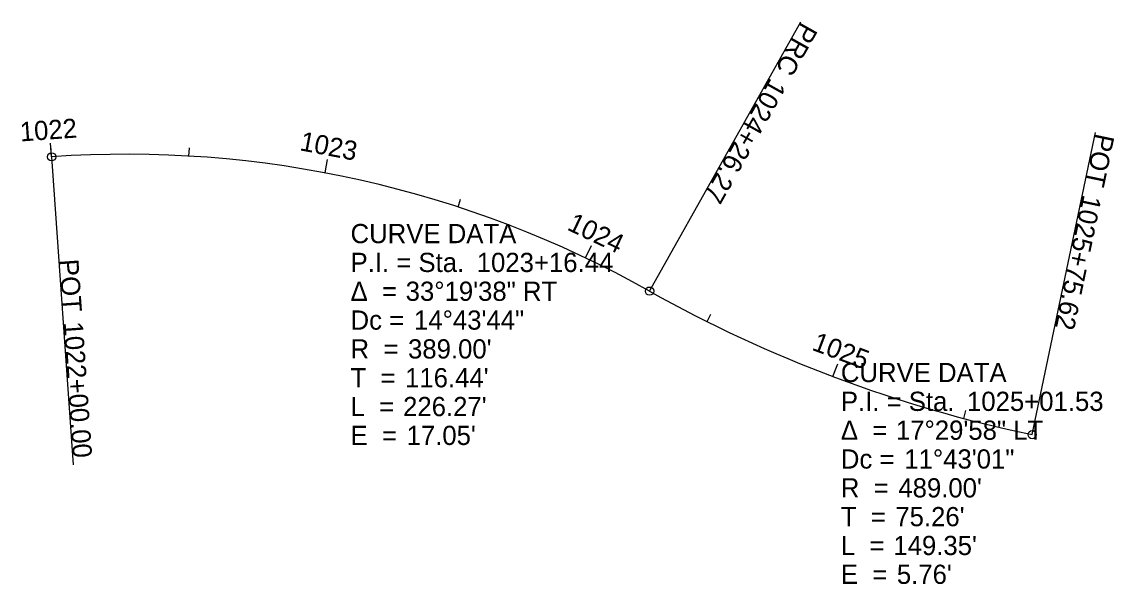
# Model space of a CAD drawing. Extents: x 2197198 to 2197596, y 661573 to 661777.
import ezdxf

# ---------------------------------------------------------------- set-up
doc = ezdxf.new("R2010")
doc.units = 0
for name, color, linetype in [('_CIVIL_CONSTRUCTION', 7, 'Continuous'), ('GE_X_Alignment', 7, 'Continuous'), ('GE_X_Alignment_1000_Curve_Data', 7, 'Continuous'), ('GE_X_Alignment_1000_Stations', 7, 'Continuous'), ('GE_X_Alignment_100_Curve_Data', 7, 'Continuous'), ('GE_X_Alignment_100_Stations', 7, 'Continuous'), ('GE_X_Alignment_500_Curve_Data', 7, 'Continuous'), ('GE_X_Alignment_500_Stations', 7, 'Continuous'), ('SC_Scratch2', 7, 'Continuous'), ('SC_Scratch5', 7, 'Continuous')]:
    doc.layers.add(name, color=color, linetype=linetype)

msp = doc.modelspace()

# ---------------------------------------------------------------- linework, layer by layer
at = {"layer": 'GE_X_Alignment'}
for p, q in [((2197426.98, 661679.27), (2197482.08, 661777.36)), ((2197566.26, 661626.99), (2197589.31, 661737.1)), ((2197209.31, 661728.18), (2197217.16, 661615.95))]:
    msp.add_line(p, q, dxfattribs=at)
for centre in [(2197209.31, 661728.18), (2197426.98, 661679.27), (2197566.26, 661626.99)]:
    msp.add_circle(centre, 1.5, dxfattribs=at)
at = {"layer": 'GE_X_Alignment_1000_Stations'}
for p, q in [((2197426.98, 661679.27), (2197482.08, 661777.36)), ((2197566.26, 661626.99), (2197589.31, 661737.1)), ((2197209.31, 661728.18), (2197217.16, 661615.95))]:
    msp.add_line(p, q, dxfattribs=at)
for centre in [(2197209.31, 661728.18), (2197426.98, 661679.27), (2197566.26, 661626.99)]:
    msp.add_circle(centre, 1.5, dxfattribs=at)
at = {"layer": 'GE_X_Alignment_100_Curve_Data'}
for p, q in [((2197426.98, 661679.27), (2197482.08, 661777.36)), ((2197566.26, 661626.99), (2197589.31, 661737.1)), ((2197209.31, 661728.18), (2197217.16, 661615.95))]:
    msp.add_line(p, q, dxfattribs=at)
for centre in [(2197209.31, 661728.18), (2197426.98, 661679.27), (2197566.26, 661626.99)]:
    msp.add_circle(centre, 1.5, dxfattribs=at)
at = {"layer": 'GE_X_Alignment_100_Stations'}
for p, q in [((2197209.31, 661728.18), (2197208.96, 661733.16)), ((2197259.28, 661728.46), (2197259.45, 661731.45)), ((2197308.86, 661722.33), (2197309.79, 661727.24)), ((2197357.26, 661709.89), (2197358.19, 661712.74)), ((2197403.66, 661691.36), (2197405.81, 661695.87)), ((2197447.94, 661668.16), (2197449.28, 661670.84)), ((2197493.73, 661648.14), (2197495.5, 661652.81)), ((2197541.33, 661632.89), (2197542.1, 661635.79))]:
    msp.add_line(p, q, dxfattribs=at)
at = {"layer": 'GE_X_Alignment_500_Curve_Data'}
for p, q in [((2197209.31, 661728.18), (2197209.1, 661731.17)), ((2197308.86, 661722.33), (2197309.42, 661725.27)), ((2197403.66, 661691.36), (2197404.95, 661694.07)), ((2197493.73, 661648.14), (2197495.5, 661652.81))]:
    msp.add_line(p, q, dxfattribs=at)
at = {"layer": 'SC_Scratch2'}
msp.add_line((2197493.73, 661648.14), (2197494.79, 661650.94), dxfattribs=at)
at = {"layer": 'SC_Scratch5'}
for centre, radius, start, end in [((2197236.45, 661340.13), 389, 60.6741, 94.0013), ((2197666.48, 662105.61), 489, 240.6741, 258.1734)]:
    msp.add_arc(centre, radius, start, end, dxfattribs=at)

# ---------------------------------------------------------------- texts
at = {"layer": '_CIVIL_CONSTRUCTION'}
for s, p in [('CURVE DATA', (2197318.14, 661696.73)), ('P.I. = Sta. ', (2197318.14, 661686.23)), ('1023+16.44', (2197364.07, 661686.23)), ('Δ  = ', (2197318.14, 661675.73)), ('33°19\'38" RT', (2197338.2, 661675.73)), ('Dc = ', (2197318.14, 661665.23)), ('14°43\'44"', (2197341.24, 661665.23)), ('R  = ', (2197318.14, 661654.73)), ("389.00'", (2197339.06, 661654.73)), ('T  = ', (2197318.14, 661644.23)), ("116.44'", (2197337.98, 661644.23)), ('CURVE DATA', (2197496.62, 661646.13)), ('L  = ', (2197318.14, 661633.73)), ("226.27'", (2197337.26, 661633.73)), ('P.I. = Sta. ', (2197496.62, 661635.63)), ('1025+01.53', (2197542.54, 661635.63)), ('Δ  = ', (2197496.62, 661625.13)), ('17°29\'58" LT', (2197516.67, 661625.13)), ('E  = ', (2197318.14, 661623.23)), ("17.05'", (2197338.53, 661623.23)), ('Dc = ', (2197496.62, 661614.63)), ('11°43\'01"', (2197519.71, 661614.63)), ('R  = ', (2197496.62, 661604.13)), ("489.00'", (2197517.54, 661604.13)), ('T  = ', (2197496.62, 661593.63)), ("75.26'", (2197516.45, 661593.63)), ('L  = ', (2197496.62, 661583.13)), ("149.35'", (2197515.73, 661583.13)), ('E  = ', (2197496.62, 661572.63)), ("5.76'", (2197517, 661572.63))]:
    msp.add_text(s, height=7, dxfattribs=at).set_placement(p)
at = {"layer": 'GE_X_Alignment'}
for s, rotation, p in [('PRC', 240.6741, (2197482.34, 661777.59)), ('1024+26.27', 240.6741, (2197470.9, 661757.22)), ('POT', 258.1734, (2197589.41, 661736.98)), ('1025+75.62', 258.1734, (2197584.73, 661714.64)), ('POT', 274.0013, (2197212.05, 661690.69)), ('1022+00.00', 274.0013, (2197213.64, 661667.92))]:
    msp.add_text(s, height=7, rotation=rotation, dxfattribs=at).set_placement(p)
at = {"layer": 'GE_X_Alignment_1000_Curve_Data'}
for s, p in [('CURVE DATA', (2197318.14, 661696.73)), ('P.I. = Sta. ', (2197318.14, 661686.23)), ('1023+16.44', (2197364.07, 661686.23)), ('Δ  = ', (2197318.14, 661675.73)), ('33°19\'38" RT', (2197338.2, 661675.73)), ('Dc = ', (2197318.14, 661665.23)), ('14°43\'44"', (2197341.24, 661665.23)), ('R  = ', (2197318.14, 661654.73)), ("389.00'", (2197339.06, 661654.73)), ('T  = ', (2197318.14, 661644.23)), ("116.44'", (2197337.98, 661644.23)), ('CURVE DATA', (2197496.62, 661646.13)), ('L  = ', (2197318.14, 661633.73)), ("226.27'", (2197337.26, 661633.73)), ('P.I. = Sta. ', (2197496.62, 661635.63)), ('1025+01.53', (2197542.54, 661635.63)), ('Δ  = ', (2197496.62, 661625.13)), ('17°29\'58" LT', (2197516.67, 661625.13)), ('E  = ', (2197318.14, 661623.23)), ("17.05'", (2197338.53, 661623.23)), ('Dc = ', (2197496.62, 661614.63)), ('11°43\'01"', (2197519.71, 661614.63)), ('R  = ', (2197496.62, 661604.13)), ("489.00'", (2197517.54, 661604.13)), ('T  = ', (2197496.62, 661593.63)), ("75.26'", (2197516.45, 661593.63)), ('L  = ', (2197496.62, 661583.13)), ("149.35'", (2197515.73, 661583.13)), ('E  = ', (2197496.62, 661572.63)), ("5.76'", (2197517, 661572.63))]:
    msp.add_text(s, height=7, dxfattribs=at).set_placement(p)
at = {"layer": 'GE_X_Alignment_1000_Stations'}
for s, rotation, p in [('PRC', 240.6741, (2197482.34, 661777.59)), ('1024+26.27', 240.6741, (2197470.9, 661757.22)), ('POT', 258.1734, (2197589.41, 661736.98)), ('1025+75.62', 258.1734, (2197584.73, 661714.64)), ('POT', 274.0013, (2197212.05, 661690.69)), ('1022+00.00', 274.0013, (2197213.64, 661667.92))]:
    msp.add_text(s, height=7, rotation=rotation, dxfattribs=at).set_placement(p)
at = {"layer": 'GE_X_Alignment_100_Curve_Data'}
for s, rotation, p in [('PRC', 240.6741, (2197482.34, 661777.59)), ('1024+26.27', 240.6741, (2197470.9, 661757.22)), ('POT', 258.1734, (2197589.41, 661736.98)), ('1025+75.62', 258.1734, (2197584.73, 661714.64)), ('POT', 274.0013, (2197212.05, 661690.69)), ('1022+00.00', 274.0013, (2197213.64, 661667.92))]:
    msp.add_text(s, height=7, rotation=rotation, dxfattribs=at).set_placement(p)
at = {"layer": 'GE_X_Alignment_100_Stations'}
for s, rotation, p in [('1022', 4.0013, (2197197.99, 661733.77)), ('1023', 349.2723, (2197299.36, 661730.61)), ('1024', 334.5433, (2197396.63, 661701.76)), ('1025', 339.313, (2197485.74, 661657.96))]:
    msp.add_text(s, height=7, rotation=rotation, dxfattribs=at).set_placement(p)
at = {"layer": 'GE_X_Alignment_500_Curve_Data'}
msp.add_text('1025', height=7, rotation=339.313, dxfattribs=at).set_placement((2197485.74, 661657.96))
at = {"layer": 'GE_X_Alignment_500_Stations'}
for s, p in [('CURVE DATA', (2197318.14, 661696.73)), ('P.I. = Sta. ', (2197318.14, 661686.23)), ('1023+16.44', (2197364.07, 661686.23)), ('Δ  = ', (2197318.14, 661675.73)), ('33°19\'38" RT', (2197338.2, 661675.73)), ('Dc = ', (2197318.14, 661665.23)), ('14°43\'44"', (2197341.24, 661665.23)), ('R  = ', (2197318.14, 661654.73)), ("389.00'", (2197339.06, 661654.73)), ('T  = ', (2197318.14, 661644.23)), ("116.44'", (2197337.98, 661644.23)), ('CURVE DATA', (2197496.62, 661646.13)), ('L  = ', (2197318.14, 661633.73)), ("226.27'", (2197337.26, 661633.73)), ('P.I. = Sta. ', (2197496.62, 661635.63)), ('1025+01.53', (2197542.54, 661635.63)), ('Δ  = ', (2197496.62, 661625.13)), ('17°29\'58" LT', (2197516.67, 661625.13)), ('E  = ', (2197318.14, 661623.23)), ("17.05'", (2197338.53, 661623.23)), ('Dc = ', (2197496.62, 661614.63)), ('11°43\'01"', (2197519.71, 661614.63)), ('R  = ', (2197496.62, 661604.13)), ("489.00'", (2197517.54, 661604.13)), ('T  = ', (2197496.62, 661593.63)), ("75.26'", (2197516.45, 661593.63)), ('L  = ', (2197496.62, 661583.13)), ("149.35'", (2197515.73, 661583.13)), ('E  = ', (2197496.62, 661572.63)), ("5.76'", (2197517, 661572.63))]:
    msp.add_text(s, height=7, dxfattribs=at).set_placement(p)

doc.saveas('drawing.dxf')
